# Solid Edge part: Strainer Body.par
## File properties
Author: rkriggs
Template: sync iso part.par
Last saved by: plm
Revision: 24
Application: Solid Edge
Density: 913.000 kg/m^3
Accuracy: 0.990
圖檔名稱: Strainer Body
圖檔編號: Strainer Body
major_rev: A
classification: Mechanical/Part
generation: 2
id: 789BB70F5B4D4A7D950021C7324AF377
thumbnail: vault:///?fileId=5E9FEC5E2A8F4EE0B44476EAE6F1F01E
authoring_tool: Solid Edge
Material: Polypropylene, general purpose
Face Style: Blue
Fill Style: ANSI34(Plastic)
Virtual Style: Green (Shiny)
Coef. of Thermal Exp: 6.8e-05
Thermal Conductivity: 2.1
Specific Heat: 1884.0
Modulus of Elasticity: 1103161120.0
Poisson's Ratio: 0.35
Yield Stress: 33094833.6
Ultimate Stress: 0.0
Elongation: 0.0
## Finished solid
Body 1: solid body, 173 faces, 483 edges, 312 vertices.
  Faces by surface: plane 94, cylinder 72, cone 7
  Edges by curve: line 308, circle 163, ellipse 12
Bounding box of the edges (mm): 114.199 x 114.199 x 57.026, from (-57.0994, -57.0994, 56.0802) to (57.0994, 57.0994, 113.1062).
Cylindrical faces by radius (mm): R0.762 x1, R1.143 x64, R50.6682 x3, R55.2139 x4
Conical faces (half-angle, radius in mm at the cone's reference point): 1 deg R49.9062 x3, 1 deg R55.2139 x1, 1 deg R57.0985 x1, 5 deg R49.2717 x1, 5 deg R53.4354 x1
Planar faces by outward normal: +x 5, +y 5, +z 7, -x 5, -y 5, -z 5, oblique 62
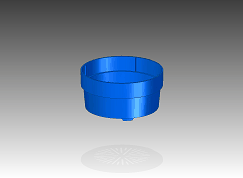
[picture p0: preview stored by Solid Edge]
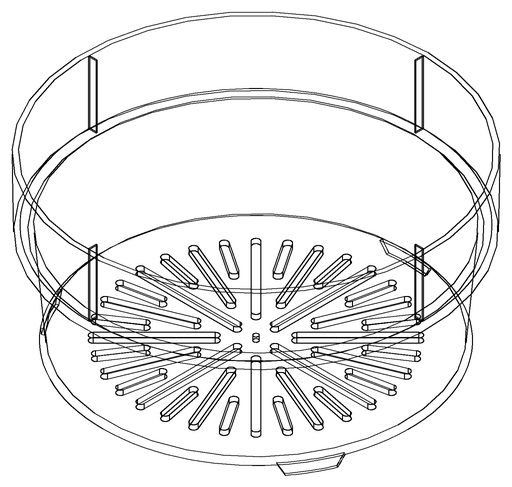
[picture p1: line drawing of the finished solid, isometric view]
